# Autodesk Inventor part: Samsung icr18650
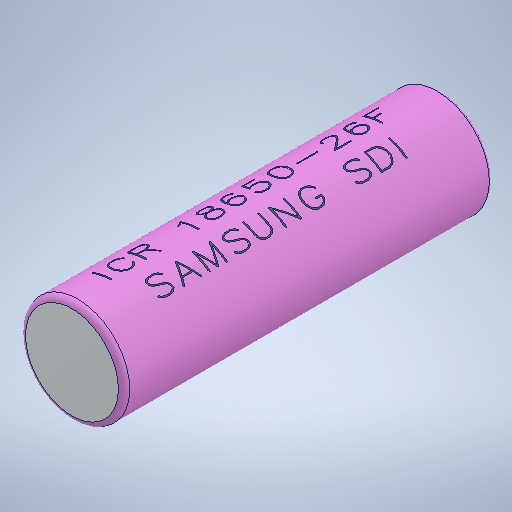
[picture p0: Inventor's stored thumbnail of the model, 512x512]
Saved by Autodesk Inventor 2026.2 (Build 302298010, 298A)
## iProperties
Created: 2015-05
Part Number: Samsung icr18650
Material: Générique
Document SubType Name: Modeling
Designer: mel
Density: 1 g/cm^3
Appearance: Par défaut
Author: mel
Sending System: SOLIDWORKS 2012
last saved by: JD
Last Saved Date: 2015-05-18
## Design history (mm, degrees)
feature "Envolver1"
node "Eje1"
node "Plano1"
node "Solide1"
